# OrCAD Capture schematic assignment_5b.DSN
size A4
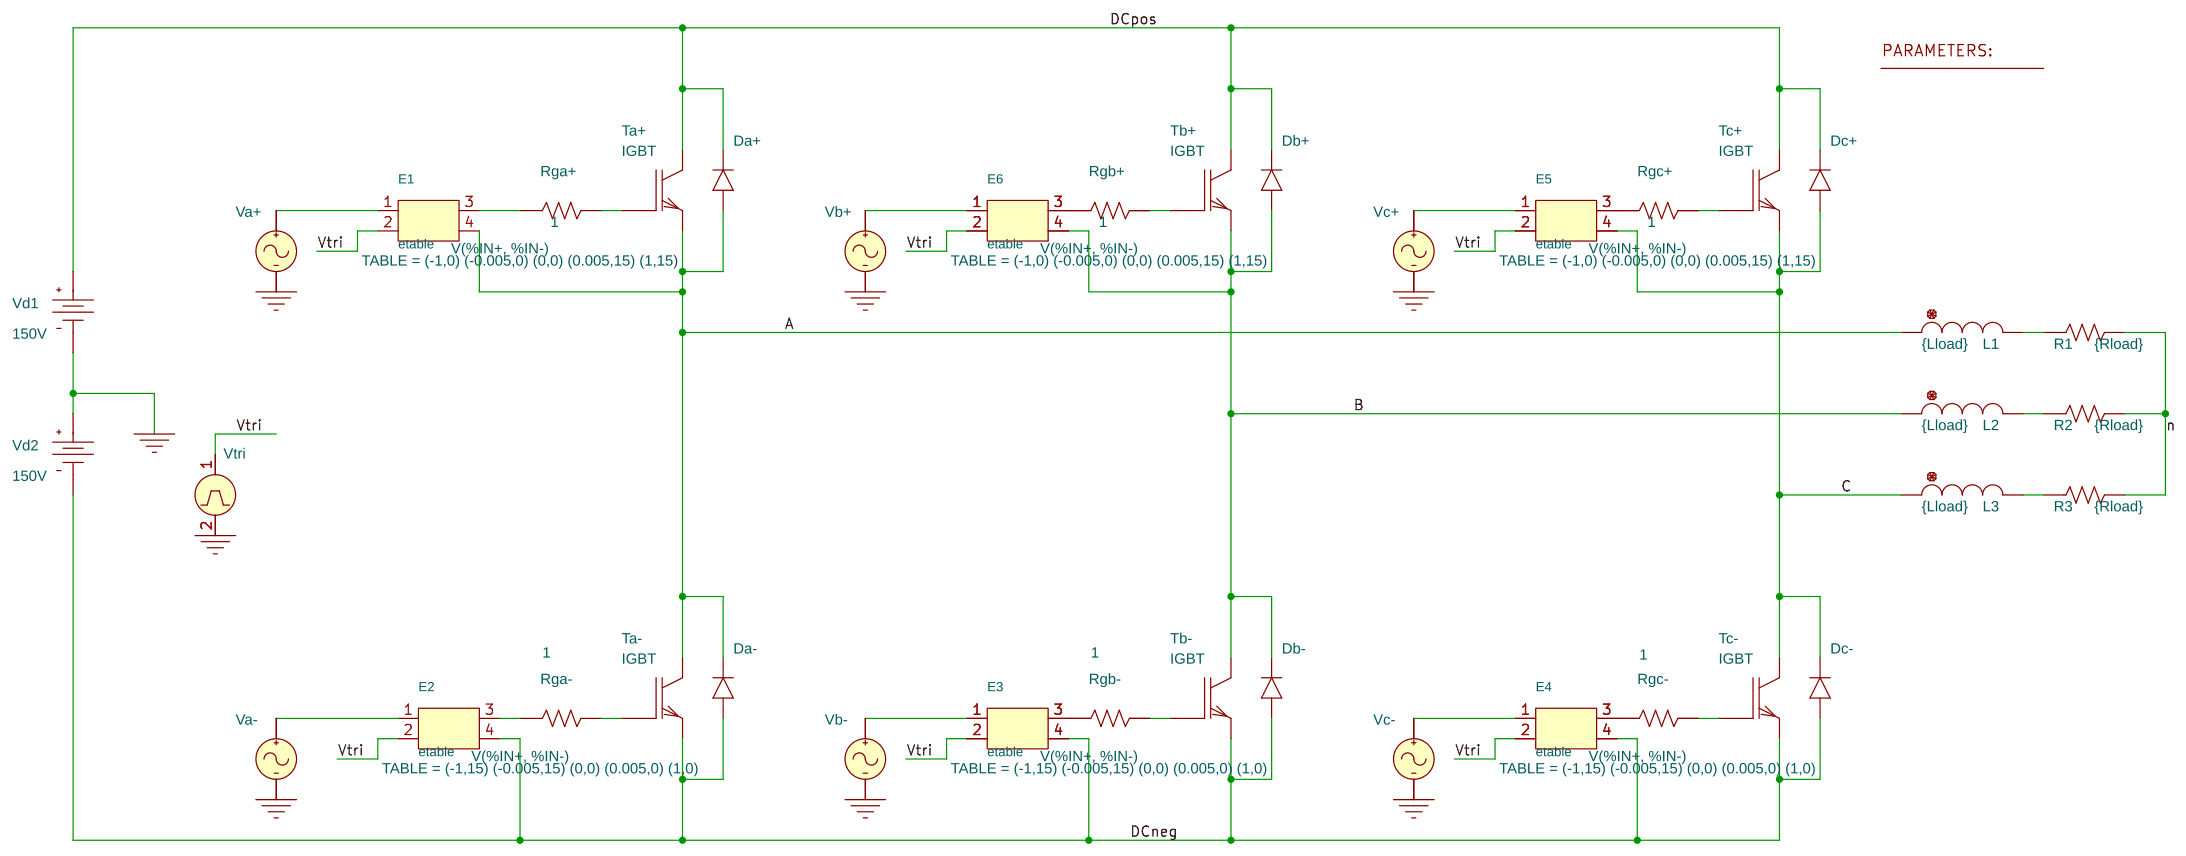
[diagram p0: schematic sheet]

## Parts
1  PARAM
Da+  d
Da-  d
Db+  d
Db-  d
Dc+  d
Dc-  d
E1  etable
E2  etable
E3  etable
E4  etable
E5  etable
E6  etable
L1  {Lload}  [DISC/.350x.175/LS.200x.100/.034]
L2  {Lload}  [DISC/.350x.175/LS.200x.100/.034]
L3  {Lload}  [DISC/.350x.175/LS.200x.100/.034]
R1  {Rload}  [AX/RC05]
R2  {Rload}  [AX/RC05]
R3  {Rload}  [AX/RC05]
Rga+  1  [AX/RC05]
Rga-  1  [AX/RC05]
Rgb+  1  [AX/RC05]
Rgb-  1  [AX/RC05]
Rgc+  1  [AX/RC05]
Rgc-  1  [AX/RC05]
Ta+  IGBT
Ta-  IGBT
Tb+  IGBT
Tb-  IGBT
Tc+  IGBT
Tc-  IGBT
Va+  VSIN
Va-  VSIN
Vb+  VSIN
Vb-  VSIN
Vc+  VSIN
Vc-  VSIN
Vd1  VDC
Vd2  VDC
Vtri  VPULSE

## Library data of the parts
1 = PARAM: FS: 1000; Lload: 1m; Vampl: 0.8; freq: 50Hz
Da+ Da- Db+ Db- Dc+ Dc- = diode
E1 E5 E6 = ETABLE: EXPR: V(%IN+, %IN-); TABLE: (-1,0) (-0.005,0) (0,0) (0.005,15) (1,15)
E2-E4 = ETABLE: EXPR: V(%IN+, %IN-); TABLE: (-1,15) (-0.005,15) (0,0) (0.005,0) (1,0)
L1 L2 = L: IC: -7A
L3 = L: IC: 14A
R1-R3 Rga+ Rga- Rgb+ Rgb- Rgc+ Rgc- = R
Ta+ Ta- Tb+ Tb- Tc+ Tc- = CM300DY-24H
Va+ = VSIN: FREQ: {freq}; VAMPL: {Vampl}; VOFF: 0
Va- = VSIN: FREQ: {freq}; PHASE: 0; VAMPL: {Vampl}; VOFF: 0
Vb+ Vb- = VSIN: FREQ: {freq}; PHASE: 120; VAMPL: {Vampl}; VOFF: 0
Vc+ Vc- = VSIN: FREQ: {freq}; PHASE: 240; VAMPL: {Vampl}; VOFF: 0
Vd1 Vd2 = VDC: DC: 150V
Vtri = VPULSE: PER: {1/FS}; PW: 100n; TD: 0; TF: {(1/FS - 0.2u)/2}; TR: {(1/FS - 0.2u)/2}; V1: -1; V2: 1

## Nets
0: Va+.2(-) Va-.2(-) Vb+.2(-) Vb-.2(-) Vc+.2(-) Vc-.2(-) Vd1.1(-) Vd2.0(+) Vtri.2(-)
A: Da+.1(A) Da-.2(K) E1.4(OUT-) L1.1 Ta+.3(E) Ta-.2(C)
B: Db+.1(A) Db-.2(K) E6.4(OUT-) L2.1 Tb+.3(E) Tb-.2(C)
C: Dc+.1(A) Dc-.2(K) E5.4(OUT-) L3.1 Tc+.3(E) Tc-.2(C)
DCneg: Da-.1(A) Db-.1(A) Dc-.1(A) E2.4(OUT-) E3.4(OUT-) E4.4(OUT-) Ta-.3(E) Tb-.3(E) Tc-.3(E) Vd2.1(-)
DCpos: Da+.2(K) Db+.2(K) Dc+.2(K) Ta+.2(C) Tb+.2(C) Tc+.2(C) Vd1.0(+)
n: R1.2 R2.2 R3.2
Vtri: E1.2(IN-) E2.2(IN-) E3.2(IN-) E4.2(IN-) E5.2(IN-) E6.2(IN-) Vtri.1(+)
N6690073: L3.2 R3.1
N6690107: L2.2 R2.1
N6691047: Rga-.2 Ta-.1(G)
N6691057: Rga+.2 Ta+.1(G)
N6691067: Rgb+.2 Tb+.1(G)
N6691073: Rgc+.2 Tc+.1(G)
N6691197: Rgb-.2 Tb-.1(G)
N6691227: Rgc-.2 Tc-.1(G)
N6691820: E1.3(OUT+) Rga+.1
N6692076: E2.3(OUT+) Rga-.1
N6694827: E1.1(IN+) Va+.1(+)
N6697382: E2.1(IN+) Va-.1(+)
N6698532: E3.1(IN+) Vb-.1(+)
N6698721: E4.1(IN+) Vc-.1(+)
N6699111: E6.1(IN+) Vb+.1(+)
N6699211: E5.1(IN+) Vc+.1(+)
N6700153: L1.2 R1.1
N6711773: E6.3(OUT+) Rgb+.1
N6711774: E3.3(OUT+) Rgb-.1
N6711775: E4.3(OUT+) Rgc-.1
N6711776: E5.3(OUT+) Rgc+.1
